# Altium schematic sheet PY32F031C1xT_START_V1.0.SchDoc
size 381 x 304 mm; SheetNumber: 1; SheetTotal: 1
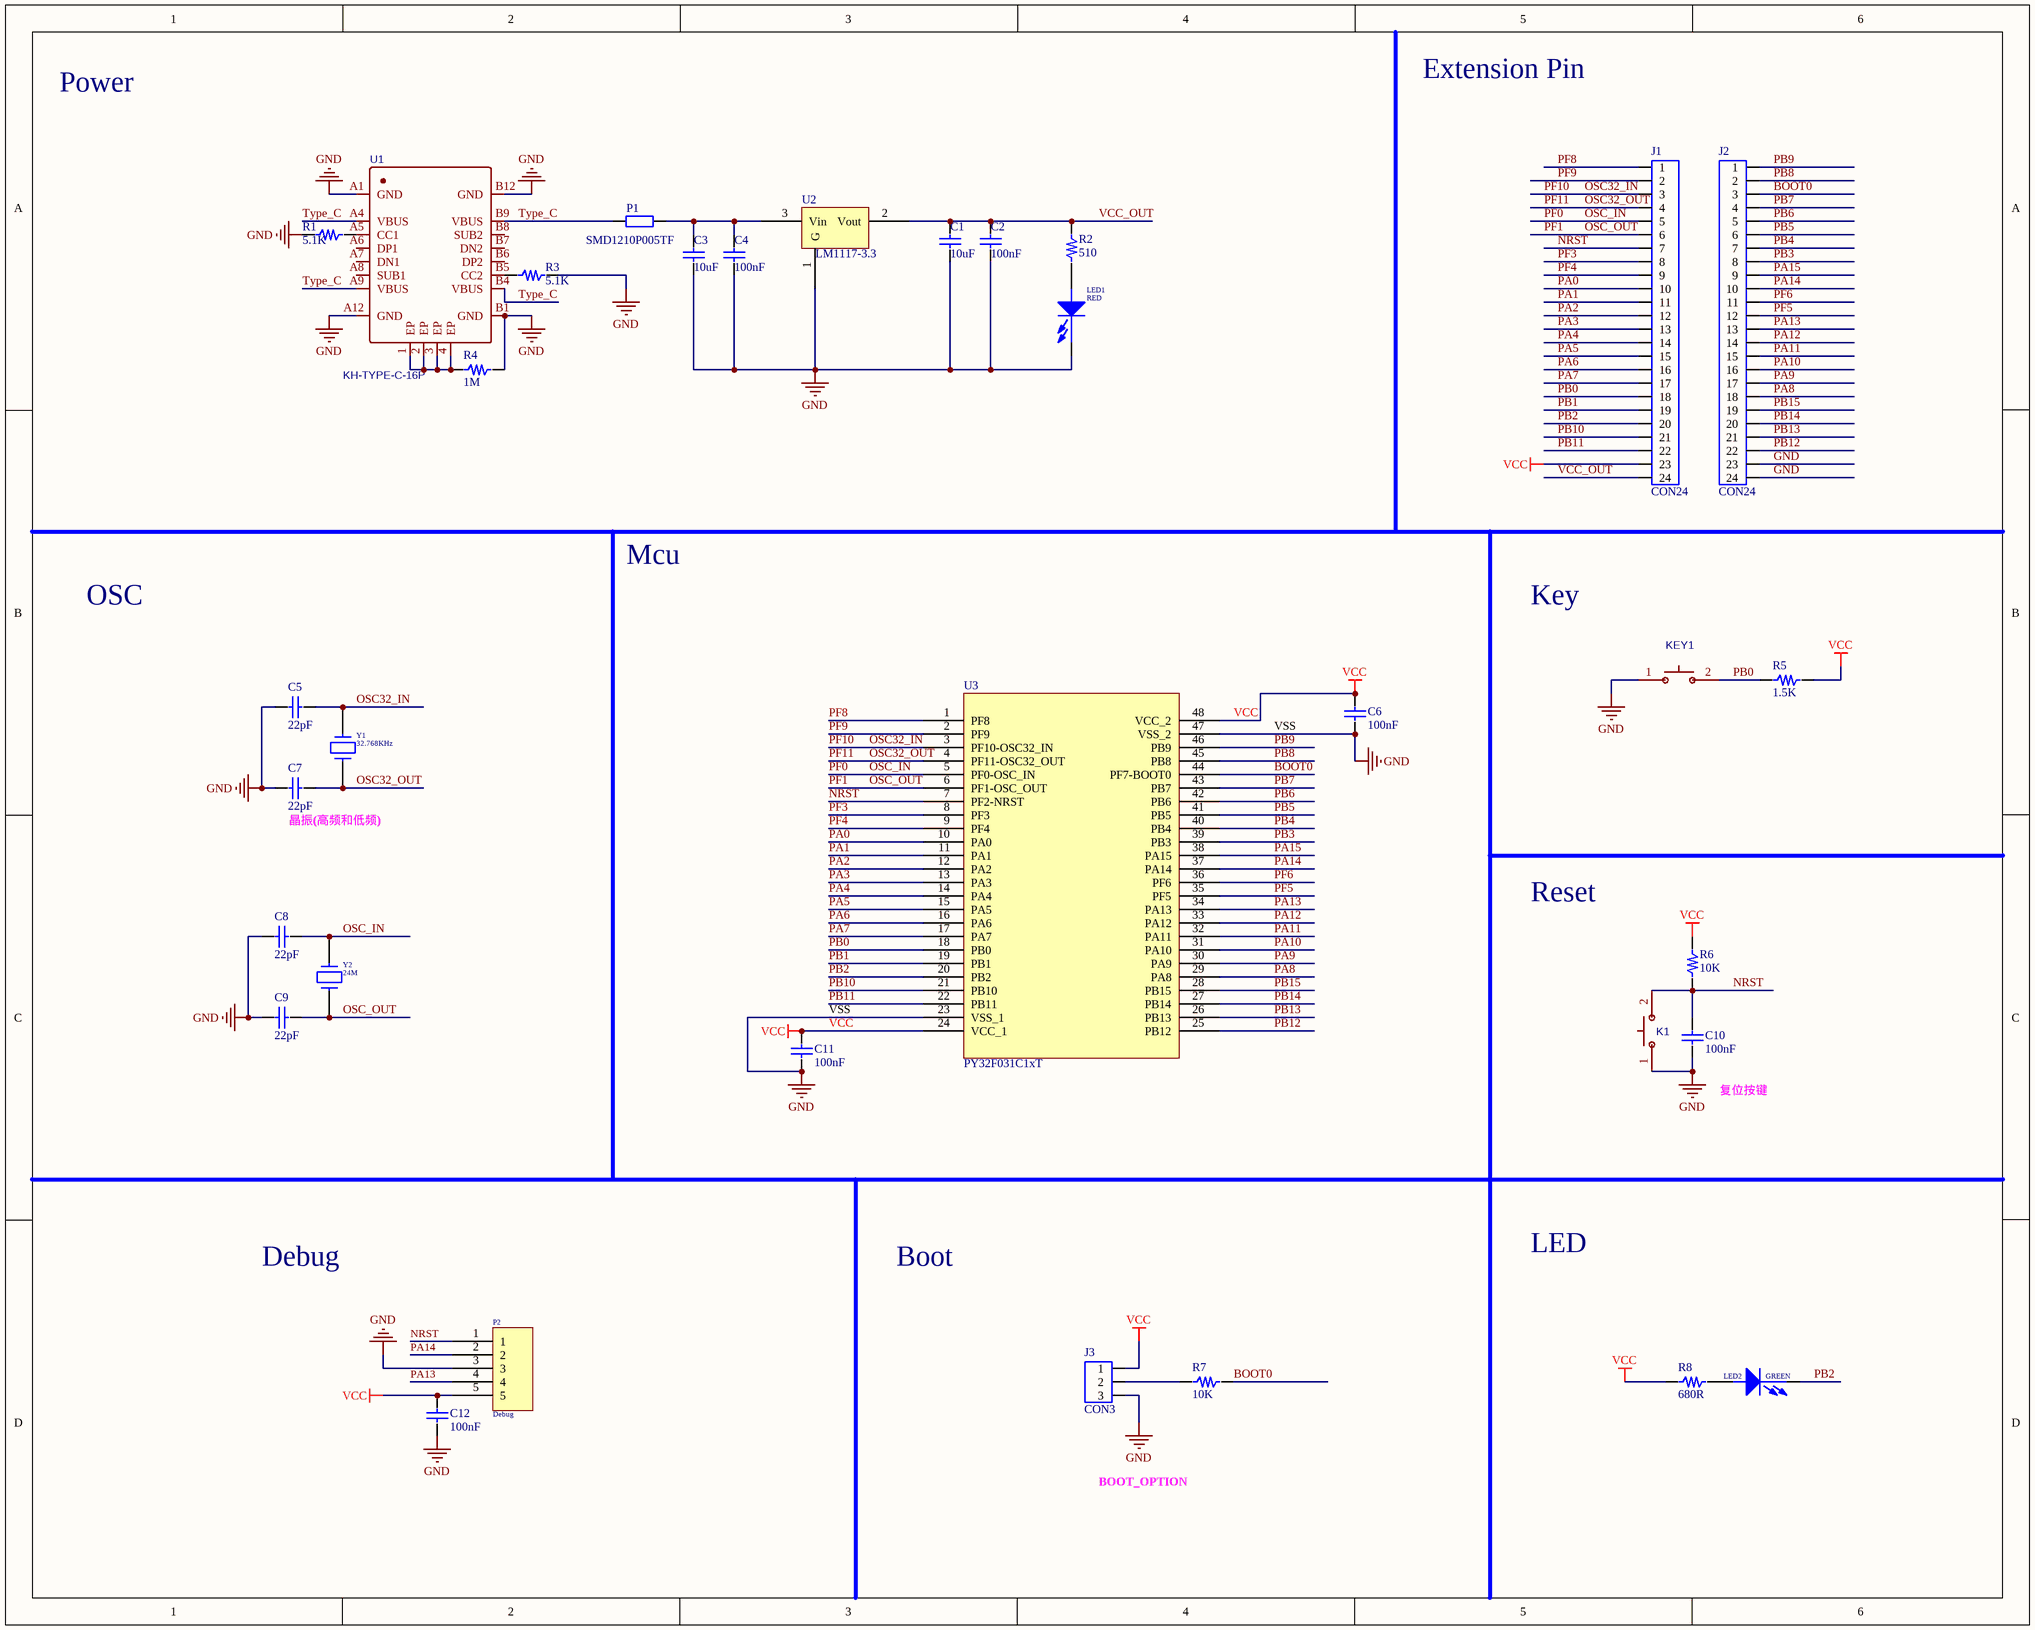
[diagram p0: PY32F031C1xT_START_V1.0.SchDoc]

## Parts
C1  10uF  [C0805]
C2  100nF  [C0603]
C3  10uF  [C0805]
C4  100nF  [C0603]
C5  22pF  [C0603]
C6  100nF  [C0603]
C7  22pF  [C0603]
C8  22pF  [C0603]
C9  22pF  [C0603]
C10  100nF  [C0603]
C11  100nF  [C0603]
C12  100nF  [C0603]
J1  CON24  [CON24]
J2  CON24  [CON24]
J3  CON3  [CON3]
K1  1TS002B-2600-5001_key  [SW]  (value not drawn)
KEY1  1TS002B-2600-5001  [SW]  (value not drawn)
LED1  RED  [0603_LED]
LED2  GREEN  [0603_LED]
P1  SMD1210P005TF  [R0805]
P2  Debug  [HDR1X5]
R1  5.1K  [R0603]
R2  510  [R0603]
R3  5.1K  [R0603]
R4  1M  [R0603]
R5  1.5K  [R0603]
R6  10K  [R0603]
R7  10K  [R0603]
R8  680R  [R0603]
U1  KH-TYPE-C-16P  [USB-C-SMD_KH-TYPE-C-16P]
U2  LM1117-3.3  [LM1117-3.3]
U3  PY32F031C1xT  [LQFP-48_L7.0-W7.0-P0.50-LS9.0-BL]
Y1  32.768KHz  [32768KHZ_2]
Y2  24M  [25MHZ_2]

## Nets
GND: C1.1 C2.1 C3.1 C4.1 C5.2 C6.2 C7.2 C8.2 C9.2 C10.1 C11.1 C12.1 J2.23 J2.24 J3.3 K1.1(A) KEY1.1(A) LED1.2(CATHODE) P2.3 R1.1 R3.2 R4.2 U1.A1(GND) U1.A12(GND) U1.B1(GND) U1.B12(GND) U2.1(G) U3.23(VSS_1) U3.47(VSS_2)  [also labelled VSS]
VCC: C6.1 C11.2 C12.2 J1.23 J3.1 P2.5 R5.2 R6.2 R8.1 U3.24(VCC_1) U3.48(VCC_2)
BOOT0: J2.3 R7.2 U3.44(PF7-BOOT0)
NRST: C10.2 J1.7 K1.2(B) P2.1 R6.1 U3.7(PF2-NRST)
OSC32_IN: C5.1 J1.3 U3.3(PF10-OSC32_IN) Y1.1  [also labelled PF10]
OSC32_OUT: C7.1 J1.4 U3.4(PF11-OSC32_OUT) Y1.2  [also labelled PF11]
OSC_IN: C8.1 J1.5 U3.5(PF0-OSC_IN) Y2.2  [also labelled PF0]
OSC_OUT: C9.1 J1.6 U3.6(PF1-OSC_OUT) Y2.1  [also labelled PF1]
PA0: J1.10 U3.10(PA0)
PA1: J1.11 U3.11(PA1)
PA2: J1.12 U3.12(PA2)
PA3: J1.13 U3.13(PA3)
PA4: J1.14 U3.14(PA4)
PA5: J1.15 U3.15(PA5)
PA6: J1.16 U3.16(PA6)
PA7: J1.17 U3.17(PA7)
PA8: J2.18 U3.29(PA8)
PA9: J2.17 U3.30(PA9)
PA10: J2.16 U3.31(PA10)
PA11: J2.15 U3.32(PA11)
PA12: J2.14 U3.33(PA12)
PA13: J2.13 P2.4 U3.34(PA13)
PA14: J2.10 P2.2 U3.37(PA14)
PA15: J2.9 U3.38(PA15)
PB0: J1.18 KEY1.2(B) R5.1 U3.18(PB0)
PB1: J1.19 U3.19(PB1)
PB2: J1.20 LED2.2(CATHODE) U3.20(PB2)
PB3: J2.8 U3.39(PB3)
PB4: J2.7 U3.40(PB4)
PB5: J2.6 U3.41(PB5)
PB6: J2.5 U3.42(PB6)
PB7: J2.4 U3.43(PB7)
PB8: J2.2 U3.45(PB8)
PB9: J2.1 U3.46(PB9)
PB10: J1.21 U3.21(PB10)
PB11: J1.22 U3.22(PB11)
PB12: J2.22 U3.25(PB12)
PB13: J2.21 U3.26(PB13)
PB14: J2.20 U3.27(PB14)
PB15: J2.19 U3.28(PB15)
PF3: J1.8 U3.8(PF3)
PF4: J1.9 U3.9(PF4)
PF5: J2.12 U3.35(PF5)
PF6: J2.11 U3.36(PF6)
PF8: J1.1 U3.1(PF8)
PF9: J1.2 U3.2(PF9)
Type_C: P1.1 U1.A4(VBUS) U1.A9(VBUS) U1.B4(VBUS) U1.B9(VBUS)
VCC_OUT: C1.2 C2.2 J1.24 R2.2 U2.2(Vout)
NetC3_2: C3.2 C4.2 P1.2 U2.3(Vin)
NetJ3_2: J3.2 R7.1
NetLED1_1: LED1.1(ANODE) R2.1
NetLED2_1: LED2.1(ANODE) R8.2
NetR1_2: R1.2 U1.A5(CC1)
NetR3_1: R3.1 U1.B5(CC2)
NetR4_1: R4.1 U1.1(EP) U1.2(EP) U1.3(EP) U1.4(EP)

Not connected (* = marked no-connect by the designer): U1 A6(DP1) A7(DN1) A8(SUB1) B6(DP2) B7(DN2) B8(SUB2)

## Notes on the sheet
- Power
- Extension Pin
- Mcu
- OSC
- Key
- (near C7) 晶振(高频和低频)
- Reset
- (near C10) 复位按键
- Debug
- Boot
- LED
- BOOT_OPTION

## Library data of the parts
C1 C3 = C0805: PCB DECAL: 0805
C2 C4-C12 = C0603: PCB DECAL: 0603
K1 = 1TS002B-2600-5001_key: BOM_Manufacturer: HYP; Contributor: LCSC
KEY1 = 1TS002B-2600-5001: BOM_Manufacturer: HYP; Contributor: LCSC
LED1 LED2 = PDI-E803_Dup1
P2 = CON5
R1-R8 = R0603: PCB DECAL: 0603
U1 = KH-TYPE-C-16P: BOM_Manufacturer: Shenzhen Kinghelm Elec; Contributor: LCSC
U3 = PY32F031C1xT: LQFP48
Y1 = CRYSTAL_1: Crystal; Value: X503225MSB2GI
Y2 = CRYSTAL: Value: X503225MSB2GI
